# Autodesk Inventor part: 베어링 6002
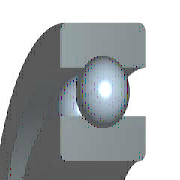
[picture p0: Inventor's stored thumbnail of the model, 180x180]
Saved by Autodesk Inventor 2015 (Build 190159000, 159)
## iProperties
IsCustomPart: 0
Created: 2015-10
Part Number: 베어링 6002
Material: 강철, 연강
Description: 깊은 그루브 볼 베어링
Document SubType Name: Modeling
Standard: KS B 2023
Designer: mdu
Standards Organization: KS
Language: ko-KR
Size Designation: 6002 - 15 x 32 x 9
Categories: <MemberInstance><Categories><Category DisplayName="샤프트 부품" InternalName="7f7aeb1f-a693-4053-b835-cee3144e0d98" Mnemonic="SHFT"><Category DisplayName="베어링" Inter
Density: 7.86 g/cm^3
Mass: 29.8124 g
Surface Area: 39.9079 cm^2
Volume: 3.79293 cm^3
Appearance: 강철
Author: mdu
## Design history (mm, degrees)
sketch "스케치" dims "d0" = 4.42 (= -0.26 x WD + 0.26 x BD)
  geometry: L1 (2.29, 11.75)-(6.71, 11.75); L2 (4.5, 11.75)-(4.5, 9.54); L3 (4.5, 11.75)-(4.5, 13.96); L4 (2.858, 10.271)-(0, 10.271); L5 (0, 7.5)-(9, 7.5); L6 (2.858, 13.229)-(0, 13.229); L7 (0, 16)-(9, 16); L8 (9, 7.5)-(9, 10.271); L9 (6.142, 10.271)-(9, 10.271); L10 (6.142, 13.229)-(9, 13.229); L11 (9, 16)-(9, 13.229); L12 (-1.4, 0)-(8.4, 0) reference; L13 (0, -0.3)-(0, 5.3) reference
  constraints: 22 end point, 4 point on line, 2 collinear, 2 perpendicular, 2 symmetric about line, 1 midpoint, 1 parallel, 14 other
  dimensions: "d9" = 15 diameter of L5 L12 (= WD); "d11" = 32 diameter of L7 L12 (= BD); "d12" = 9 distance between parallel lines of L8 L13 (= KB); "d13" = 20.542 diameter of L9 L12 (= 0.326 x BD + 0.674 x WD)
revolve "본체" stored, may be unused: angle "d6" = 90 deg
revolve "볼" stored, may be unused: angle "d7" = 90 deg
pattern_circular "IDS_ARRAYBALL[SIMPL:T]" dims angle "d3" = 360 deg
body "Solid1"
fillet "모깎기1" dims "d1" = 0.3 (= KRS)
other parameters: "WD" = 15 [user parameter; used in 5 equation terms], "BD" = 32 [user parameter; used in 5 equation terms], "KB" = 9 [user parameter; used in 1 equation term], "KRS" = 0.3 [user parameter; used in 1 equation term], "d4" = 0, "d5" = 0, "d8" = 0, "d14" = 0, "d15" = 0, "BBA" = 0 [user parameter], "BC0" = 2850000 [user parameter], "BC" = 5590000 [user parameter], "BR" = 16 (= 0.5 x BD) [user parameter], "WR" = 7.5 (= 0.5 x WD) [user parameter]
